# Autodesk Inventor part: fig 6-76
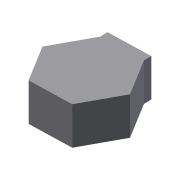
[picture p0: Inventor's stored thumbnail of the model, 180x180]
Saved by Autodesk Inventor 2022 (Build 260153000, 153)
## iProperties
Created: 2009-03
Part Number: fig 6-76
Document SubType Name: Modeling
Designer: Sham
Density: 1 g/cm^3
Material: Generic
Appearance: Default
Author: Sham
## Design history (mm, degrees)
sketch "Sketch5"
  geometry: L1 (-5.929, 9.627)-(5.372, 9.948); L2 (5.372, 9.948)-(11.301, 0.321); L3 (11.301, 0.321)-(5.929, -9.627); L4 (5.929, -9.627)-(-5.372, -9.948); L5 (-5.372, -9.948)-(-11.301, -0.321); L6 (-11.301, -0.321)-(-5.929, 9.627); 1 further point
  constraints: 12 end point, 13 other
extrude "Extrusion3" new body sketch "Sketch5" distance "d13" = 10; taper "d14" = 0 deg
thicken "Thicken2" dims "d15" = 2, "d16" = 2
body "Solid4"
